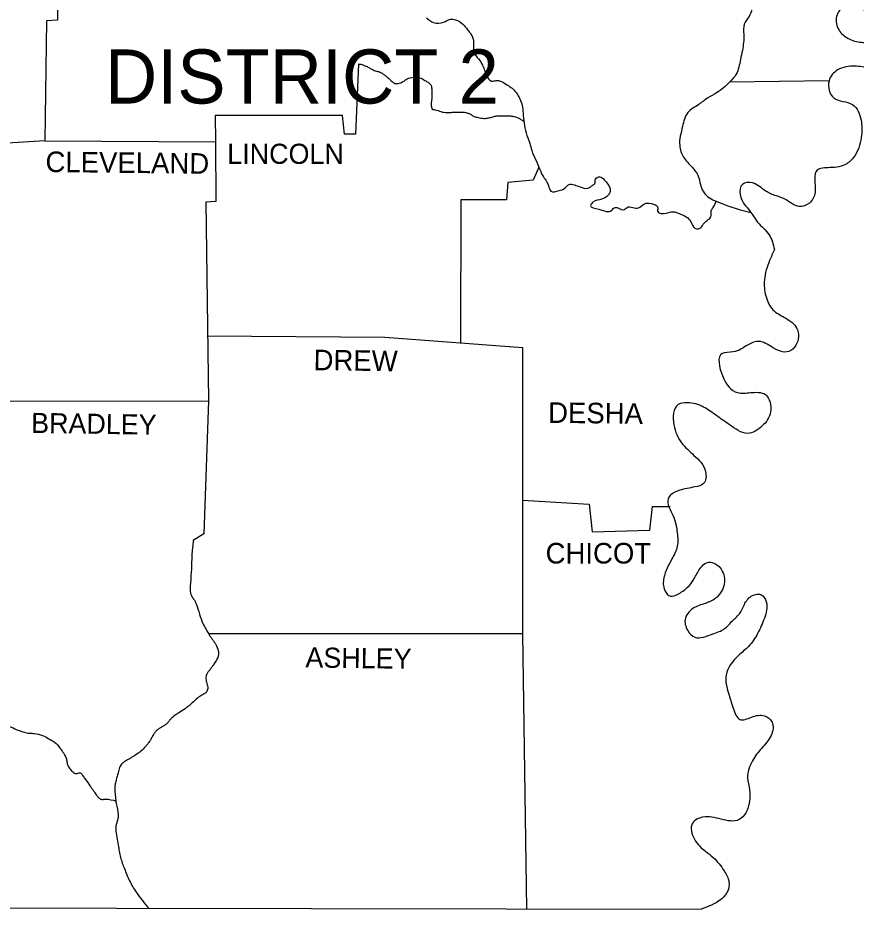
# Model space of a CAD drawing. Extents: x 1720274 to 1751788, y 372074 to 391887.
# Drawn here: x 1747309 to 1749152, y 384835 to 386795 of the extents above; entities that cross this region are included whole.
import ezdxf

# ---------------------------------------------------------------- set-up
doc = ezdxf.new("R2010")
doc.units = 0
doc.layers.add('1', color=7, linetype='Continuous')
doc.layers.add('Default', color=7, linetype='Continuous')

msp = doc.modelspace()

# ---------------------------------------------------------------- linework, layer by layer
at = {"layer": '1'}
for points in [[(1747368.5, 386524.1), (1747214.6, 386514.6)], [(1747368.5, 386524.1), (1747743.5, 386521.9)], [(1747743.5, 386521.9), (1747744.3, 386390.4), (1747722.1, 386389.3), (1747728.5, 385952.5)], [(1748844.3, 386391.4), (1748867.8, 386382.2), (1748894.8, 386372.8), (1748920.5, 386366.2)], [(1747728.5, 385952.5), (1747717.9, 385659.8), (1747694.8, 385645.1)], [(1744951.6, 385692.5), (1744953.7, 384840.9), (1748811.6, 384834.5)]]:
    msp.add_lwpolyline(points, dxfattribs=at)
for points in [[(1749697.9, 387677.8), (1749673.7, 387647.2), (1749637.9, 387666.2), (1749637.9, 387691.5), (1749643.2, 387717.8), (1749630.6, 387734.6), (1749608.5, 387727.2), (1749608.5, 387694.6), (1749606.4, 387663), (1749600, 387617.8), (1749614.8, 387604.1), (1749648.5, 387599.9), (1749672.7, 387593.6), (1749687.4, 387569.3), (1749686.4, 387539.9), (1749674.8, 387511.5), (1749657.9, 387488.3), (1749631.6, 387479.9), (1749610.6, 387493.6), (1749602.1, 387520.9), (1749592.7, 387545.1), (1749574.8, 387563), (1749555.8, 387543), (1749551.6, 387506.2), (1749552.7, 387474.6), (1749552.7, 387431.5), (1749580, 387403), (1749596.9, 387370.4), (1749591.6, 387340.9), (1749571.6, 387306.2), (1749563.2, 387275.7), (1749554.8, 387234.6), (1749555.8, 387189.3), (1749548.5, 387145.1), (1749533.7, 387115.7), (1749506.4, 387091.4), (1749488.5, 387075.7), (1749473.7, 387059.9), (1749466.4, 387028.3), (1749461.1, 387006.2), (1749441.1, 386979.9), (1749425.3, 386977.8), (1749412.7, 386988.3), (1749408.5, 387006.2), (1749408.5, 387024.1), (1749400, 387042), (1749373.7, 387049.3), (1749352.7, 387048.3), (1749343.2, 387033.5), (1749356.9, 386992.5), (1749362.1, 386966.2), (1749354.8, 386930.4), (1749359, 386926.2), (1749321.1, 386906.2), (1749290.6, 386903), (1749265.3, 386895.6), (1749241.1, 386879.9), (1749229.5, 386856.7), (1749212.7, 386837.8), (1749197.9, 386819.9), (1749177.9, 386811.4), (1749155.8, 386815.6), (1749126.4, 386818.8), (1749109.5, 386797.8), (1749114.8, 386767.2), (1749134.8, 386749.3), (1749164.2, 386740.9), (1749194.8, 386743), (1749224.3, 386746.2), (1749251.6, 386731.4), (1749246.4, 386703), (1749220, 386689.3), (1749181.1, 386685.1), (1749149.5, 386688.3), (1749111.6, 386679.9), (1749092.7, 386655.6), (1749103.2, 386618.8), (1749144.3, 386604.1), (1749163.2, 386569.3), (1749164.2, 386536.7), (1749150.6, 386493.5), (1749131.6, 386473.5), (1749094.8, 386465.1), (1749066.4, 386459.8), (1749062.1, 386411.4), (1749049.5, 386387.2), (1749027.4, 386379.8), (1748995.8, 386395.6), (1748976.9, 386403), (1748953.7, 386413.5), (1748924.3, 386431.4), (1748902.1, 386428.3), (1748908.5, 386382), (1748910.6, 386379.8), (1748935.8, 386345.1), (1748961.1, 386317.7), (1748972.7, 386285.1)], [(1748607.4, 387338.8), (1748610.6, 387295.7), (1748635.8, 387289.3), (1748646.4, 387277.8), (1748651.6, 387253.6), (1748669.5, 387243), (1748693.7, 387228.3), (1748708.5, 387217.8), (1748719, 387200.9), (1748725.3, 387173.5), (1748742.1, 387155.7), (1748765.3, 387147.2), (1748782.1, 387127.2), (1748792.7, 387098.8), (1748809.5, 387086.2), (1748826.4, 387064.1), (1748834.8, 387054.6), (1748849.5, 387029.3), (1748864.3, 387016.7), (1748874.8, 387009.3), (1748891.6, 387004.1), (1748912.7, 386990.4), (1748926.4, 386969.3), (1748926.4, 386953.5), (1748921.1, 386929.3), (1748916.9, 386904.1), (1748914.8, 386875.6), (1748912.7, 386850.4), (1748922.1, 386829.3), (1748916.9, 386797.8), (1748906.4, 386780.9), (1748905.3, 386757.7), (1748902.1, 386723), (1748897.9, 386703), (1748888.5, 386670.4), (1748874.8, 386653.5)], [(1748874.8, 386653.5), (1748845.3, 386629.3), (1748826.4, 386618.8), (1748806.4, 386604.1), (1748782.1, 386586.2), (1748770.6, 386555.6), (1748764.3, 386513.5), (1748772.7, 386488.3), (1748791.6, 386466.2), (1748804.2, 386448.3), (1748813.7, 386416.7), (1748836.9, 386394.6), (1748844.3, 386391.4)], [(1748972.7, 386285.1), (1748962.1, 386260.9), (1748950.6, 386218.8), (1748953.7, 386183), (1748969.5, 386152.5), (1748994.8, 386135.6), (1749022.1, 386111.4), (1749020, 386074.6), (1749004.3, 386060.9), (1748967.4, 386070.4), (1748939, 386083), (1748914.8, 386075.6), (1748882.1, 386059.8), (1748857.9, 386056.7), (1748859, 386006.2), (1748891.6, 385970.4), (1748920, 385970.4), (1748952.7, 385966.2), (1748964.2, 385928.3), (1748945.3, 385896.7), (1748913.7, 385880.9), (1748873.7, 385899.8), (1748845.3, 385919.8), (1748816.9, 385938.8), (1748781.1, 385948.3), (1748761.1, 385944), (1748751.6, 385899.8), (1748768.5, 385859.8), (1748795.8, 385832.5), (1748821.1, 385796.7), (1748816.9, 385770.4), (1748797.9, 385763), (1748764.3, 385755.6), (1748744.2, 385745.1), (1748739, 385736.7), (1748749.5, 385700.9), (1748759, 385661.9), (1748759, 385632.5), (1748747.4, 385605.1), (1748729.5, 385563), (1748731.6, 385535.6), (1748744.2, 385523), (1748760, 385527.2), (1748781.1, 385541.9), (1748794.8, 385558.8), (1748806.4, 385579.8), (1748828.5, 385597.7), (1748855.8, 385581.9), (1748862.1, 385549.3), (1748846.4, 385520.9), (1748824.3, 385508.2), (1748796.9, 385497.7), (1748776.9, 385474.6), (1748782.1, 385447.2), (1748797.9, 385432.5), (1748836.9, 385439.8), (1748863.2, 385451.4), (1748877.9, 385466.1), (1748895.8, 385484), (1748905.3, 385501.9), (1748919, 385520.9), (1748943.2, 385526.1), (1748954.8, 385510.3), (1748950.6, 385474.6), (1748935.8, 385440.9), (1748915.8, 385412.5), (1748893.7, 385392.5), (1748866.4, 385349.3), (1748871.6, 385309.3), (1748882.1, 385276.7), (1748896.9, 385251.4), (1748922.1, 385256.7), (1748950.6, 385259.8), (1748967.4, 385246.1), (1748965.3, 385216.7), (1748944.2, 385188.2), (1748924.3, 385160.9), (1748913.7, 385123), (1748917.9, 385096.7), (1748917.9, 385072.4), (1748909.5, 385046.1), (1748894.8, 385031.4), (1748855.8, 385032.4), (1748814.8, 385036.7), (1748792.7, 385024), (1748796.9, 384988.2), (1748821.1, 384961.9), (1748837.9, 384948.2), (1748862.1, 384918.8), (1748872.7, 384894.5), (1748869.5, 384873.5), (1748854.8, 384855.6), (1748811.6, 384834.5)], [(1747694.8, 385645.1), (1747691.6, 385612.5), (1747690.6, 385581.9), (1747688.5, 385552.5), (1747687.9, 385541.4), (1747687.9, 385535.9), (1747688.5, 385530.3), (1747690.6, 385524), (1747694.2, 385518.1), (1747698.1, 385512.3), (1747701.1, 385506.1), (1747708.5, 385483), (1747715.8, 385463), (1747730.6, 385436.7), (1747733.8, 385431.6), (1747737.4, 385426.7), (1747740.9, 385421.8), (1747744.3, 385416.7), (1747749.6, 385402.5), (1747750.1, 385395.1), (1747748.5, 385388.2), (1747740, 385373.5), (1747736.2, 385367.9), (1747732.1, 385362.4), (1747728, 385357), (1747724.3, 385351.4), (1747722.5, 385341.8), (1747724.7, 385330.8), (1747726.5, 385320.1), (1747723.2, 385311.4), (1747721, 385309.5), (1747718.7, 385307.8), (1747713.8, 385304.9), (1747708.9, 385302), (1747704.2, 385298.8), (1747692.3, 385288), (1747686.3, 385282.7), (1747680, 385277.7), (1747666.4, 385268.2), (1747651.6, 385258.8), (1747647.3, 385255), (1747643.5, 385250.6), (1747639.8, 385246.1), (1747635.8, 385241.9), (1747630.2, 385237.8), (1747624.1, 385234.3), (1747618, 385230.6), (1747612.7, 385226.1), (1747608, 385220), (1747604.1, 385213.1), (1747600.3, 385206.2), (1747595.8, 385199.8), (1747591.5, 385194.5), (1747587, 385189.2), (1747576.9, 385179.8), (1747561.1, 385169.3), (1747555.6, 385165.9), (1747550, 385162.7), (1747541.7, 385157.6), (1747539, 385155.6), (1747535.2, 385151.3), (1747532.7, 385146.1), (1747529.5, 385134.6), (1747526.7, 385124.8), (1747524.2, 385115.1), (1747522.5, 385105.4), (1747522.1, 385095.6), (1747523.4, 385081.4), (1747525.3, 385067.2), (1747529.5, 385041.9), (1747529, 385034), (1747526.9, 385026.1), (1747524.7, 385018.2), (1747524.3, 385010.3), (1747529.5, 384975.6), (1747534.8, 384948.2), (1747543.2, 384924), (1747554.8, 384896.6), (1747561.6, 384883.8), (1747569.5, 384871.4), (1747582.7, 384853.4), (1747597.2, 384836.5)]]:
    msp.add_spline(points, degree=3, dxfattribs=at)
at = {"layer": 'Default'}
msp.add_line((1748874.8, 386653.6), (1749093.1, 386656.9), dxfattribs=at)
for points in [[(1747402.2, 387216.7), (1747395.8, 386789.3), (1747371.6, 386788.3), (1747368.5, 386524.1)], [(1748057.9, 386693.5), (1748051.6, 386538.8), (1748027.4, 386538.8), (1748023.2, 386579.9), (1747743.2, 386579.9), (1747743.5, 386521.9)], [(1748454.8, 386466.2), (1748442.1, 386437.7), (1748386.4, 386432.5), (1748383.2, 386394.6), (1748283.2, 386394.6), (1748282.1, 386079.8)], [(1747725.3, 386095.6), (1748115.8, 386092.5), (1748419, 386069.3)], [(1748419, 386069.3), (1748419, 385439.8), (1748427.4, 384835.2)], [(1747252.7, 385951.4), (1747728.5, 385952.5)], [(1748419, 385733.8), (1748565.3, 385725.1), (1748571.6, 385664), (1748699, 385668.2), (1748704.3, 385719.8), (1748743.6, 385719.8)], [(1747727.9, 385440.9), (1748419, 385440.9)]]:
    msp.add_lwpolyline(points, dxfattribs=at)
for points in [[(1748207.4, 386794.6), (1748223.2, 386784.1), (1748245.3, 386785.1), (1748260, 386791.4), (1748271.6, 386790.4), (1748287.4, 386780.9), (1748297.9, 386768.3), (1748305.3, 386758.8), (1748310.6, 386744.1), (1748310.6, 386730.4), (1748315.8, 386711.4), (1748322.1, 386704.1), (1748330.6, 386690.4), (1748335.8, 386677.7), (1748339, 386669.3), (1748350.6, 386655.6), (1748361.1, 386656.7), (1748370.6, 386655.6), (1748383.2, 386648.3), (1748402.1, 386633.5), (1748405.3, 386629.3), (1748417.9, 386602), (1748420, 386585.1), (1748422.1, 386563), (1748426.4, 386542), (1748434.8, 386518.8), (1748439, 386503), (1748448.5, 386480.9), (1748454.8, 386466.2), (1748463.2, 386447.2), (1748475.8, 386426.2), (1748481.1, 386413.5), (1748499, 386414.6), (1748511.6, 386419.8), (1748521.1, 386428.3), (1748532.7, 386427.2), (1748545.3, 386423), (1748562.1, 386419.8), (1748572.7, 386426.2), (1748577.9, 386430.4), (1748579, 386439.8), (1748588.5, 386445.1), (1748599, 386437.7), (1748610.6, 386420.9), (1748610.6, 386410.4), (1748606.4, 386404.1), (1748592.7, 386395.6), (1748573.7, 386389.3), (1748568.5, 386382), (1748586.4, 386373.5), (1748614.8, 386371.4), (1748622.1, 386377.7), (1748641.1, 386372.5), (1748648.5, 386377.7), (1748673.7, 386376.7), (1748685.3, 386385.1), (1748708.5, 386384.1), (1748715.8, 386378.8), (1748715.8, 386369.3), (1748734.8, 386365.1), (1748748.5, 386368.3), (1748766.4, 386363), (1748782.1, 386354.6), (1748790.6, 386343), (1748801.1, 386330.4), (1748810.6, 386333.5), (1748817.9, 386343), (1748833.7, 386359.8), (1748833.7, 386370.4), (1748837.9, 386377.7), (1748844.3, 386391.4)], [(1748057.9, 386693.5), (1748062.8, 386692.5), (1748067.6, 386691.1), (1748076.9, 386687.2), (1748080.4, 386685.4), (1748083.8, 386683.5), (1748087.1, 386681.6), (1748090.6, 386679.9), (1748095, 386678.2), (1748099.6, 386676.9), (1748104.1, 386675.5), (1748108.5, 386673.5), (1748114.4, 386669.5), (1748120, 386665.1), (1748124, 386661.7), (1748127.9, 386658.1), (1748131.7, 386654.6), (1748133.7, 386652.9), (1748135.8, 386651.4), (1748140.2, 386649.9), (1748145.1, 386650.2), (1748150.1, 386651.7), (1748154.8, 386653.5), (1748158.2, 386655.5), (1748161.5, 386657.9), (1748164.8, 386660.3), (1748168.5, 386662), (1748182.1, 386664.1), (1748192.7, 386663), (1748204.2, 386656.7), (1748211.1, 386652.8), (1748214.3, 386650.4), (1748215.6, 386649), (1748216.3, 386648.1), (1748216.9, 386647.2), (1748218.9, 386640.5), (1748219, 386637), (1748219, 386633.5), (1748219, 386617.7), (1748219, 386595.6), (1748219.8, 386594.1), (1748221.7, 386593.3), (1748226.4, 386592.5), (1748239.4, 386588.4), (1748252.7, 386586.2), (1748257.1, 386586.3), (1748261.6, 386586.6), (1748266.1, 386587), (1748270.6, 386587.2), (1748279, 386587.4), (1748287.4, 386587.2), (1748294.3, 386586.2), (1748297.7, 386585.2), (1748301.1, 386584.1), (1748304.1, 386582.6), (1748306.9, 386580.8), (1748309.7, 386579.1), (1748312.7, 386577.7), (1748321.1, 386575.6), (1748333.7, 386573.5), (1748344.3, 386574.6), (1748348.7, 386575.7), (1748353.2, 386577.1), (1748357.6, 386578.3), (1748362.1, 386578.8), (1748372.7, 386578.8), (1748389.5, 386578.8), (1748394.8, 386578.5), (1748397.4, 386578.1), (1748400, 386577.7), (1748411.3, 386573.6), (1748416.6, 386570.3), (1748421.7, 386566.8)], [(1746645.3, 385401.9), (1746662.1, 385413.5), (1746677.9, 385419.8), (1746685.8, 385418.5), (1746689.7, 385417.5), (1746693.7, 385416.7), (1746710.6, 385414.6), (1746714.3, 385414.7), (1746717.9, 385415.5), (1746721.6, 385416.3), (1746725.3, 385416.7), (1746744.3, 385413.5), (1746748.5, 385411.4), (1746752.3, 385408.9), (1746756.1, 385406.3), (1746760, 385404), (1746768.7, 385399.3), (1746777.9, 385396.7), (1746795.8, 385396.7), (1746811.6, 385396.7), (1746815.4, 385395.3), (1746818.6, 385392.3), (1746821.7, 385389.1), (1746825.3, 385387.2), (1746831.5, 385386.3), (1746838, 385386.1), (1746844.4, 385386.7), (1746850.6, 385388.2), (1746855.8, 385390.3), (1746861.1, 385392.5), (1746866.3, 385394.7), (1746871.6, 385396.7), (1746892.7, 385403), (1746899.8, 385405.1), (1746907.1, 385407), (1746914.3, 385407.6), (1746917.7, 385407.2), (1746921.1, 385406.1), (1746934.2, 385398), (1746946.4, 385388.2), (1746955.4, 385381), (1746964.2, 385373.5), (1746979, 385356.7), (1746981.9, 385352.1), (1746984.2, 385347.2), (1746986.6, 385342.4), (1746989.5, 385337.7), (1747001.1, 385327.2), (1747005.7, 385324.8), (1747010.4, 385322.8), (1747020, 385319.8), (1747034.8, 385316.7), (1747052.7, 385311.4), (1747057.8, 385310), (1747060.1, 385308.9), (1747062.1, 385307.2), (1747065.1, 385302.5), (1747067.1, 385297.4), (1747068.7, 385292.2), (1747070.6, 385287.2), (1747072, 385283.7), (1747073.2, 385280.3), (1747075.6, 385273.4), (1747078.9, 385266.5), (1747081.3, 385263.2), (1747082.7, 385261.5), (1747084.3, 385259.8), (1747090.6, 385254.6), (1747097.2, 385251.1), (1747103.9, 385249.6), (1747110.6, 385250.3), (1747118.7, 385253.2), (1747126.8, 385256.6), (1747135, 385260.1), (1747143.2, 385263), (1747169.5, 385270.3), (1747188.5, 385276.7), (1747200, 385280.9), (1747202.6, 385281.4), (1747205.3, 385281.4), (1747208, 385281.5), (1747210.6, 385281.9), (1747210.7, 385282.1), (1747210.4, 385282.3), (1747209, 385282.9), (1747207.6, 385283.5), (1747207.3, 385283.8), (1747207.4, 385284), (1747210.4, 385285.5), (1747213.7, 385286.7), (1747220, 385287.2), (1747223.1, 385286), (1747226.2, 385284.1), (1747231.6, 385278.8), (1747233.6, 385275.9), (1747235.3, 385272.9), (1747237.1, 385270), (1747239, 385267.2), (1747251.6, 385250.3), (1747257.1, 385242.9), (1747260, 385239.3), (1747263.2, 385235.6), (1747265.8, 385233.5), (1747268.7, 385231.9), (1747271.8, 385230.9), (1747274.8, 385230.3), (1747277.7, 385231.3), (1747280.5, 385233.7), (1747283.4, 385236.1), (1747286.4, 385236.7), (1747302.1, 385231.4), (1747315.8, 385226.1), (1747331.6, 385221.9), (1747335, 385221.5), (1747338.4, 385221.3), (1747341.9, 385221.2), (1747345.3, 385220.9), (1747363.2, 385216.7), (1747376.9, 385209.3), (1747389.5, 385201.9), (1747402.1, 385188.2), (1747414.8, 385167.2), (1747416.2, 385163.1), (1747416.9, 385158.9), (1747417.6, 385154.5), (1747419, 385150.3), (1747425.2, 385140.9), (1747429.3, 385137), (1747433.7, 385133.5), (1747437.1, 385132.9), (1747440.9, 385133.8), (1747444.6, 385134.6), (1747447.4, 385133.5), (1747452.5, 385126.7), (1747457.5, 385119.9), (1747467.4, 385106.1), (1747474.8, 385095.6), (1747481.6, 385085.5), (1747485.6, 385080.8), (1747487.9, 385078.6), (1747490.6, 385076.7), (1747493.3, 385075.8), (1747496.3, 385076), (1747499.2, 385076.6), (1747502.1, 385076.7), (1747524.6, 385072.4)]]:
    msp.add_spline(points, degree=3, dxfattribs=at)

# ---------------------------------------------------------------- texts
for s, height, p in [('DISTRICT 2', 118.95, (1747500.5, 386606.1)), ('LINCOLN', 44.21, (1747769.5, 386473.5)), ('CHICOT', 45.27, (1748469.5, 385594.6))]:
    msp.add_text(s, height=height, dxfattribs=at).set_placement(p)
for s, height, rotation, p in [('CLEVELAND', 45.27, 359.3376, (1747369.5, 386455.6)), ('DREW', 45.26, 359.2258, (1747959, 386019.8)), ('DESHA', 45.26, 359.3704, (1748474.8, 385904)), ('BRADLEY', 44.2, 359.1449, (1747337.9, 385881.9)), ('ASHLEY', 44.22, 359.2361, (1747941.1, 385366.1))]:
    msp.add_text(s, height=height, rotation=rotation, dxfattribs=at).set_placement(p)

doc.saveas('drawing.dxf')
